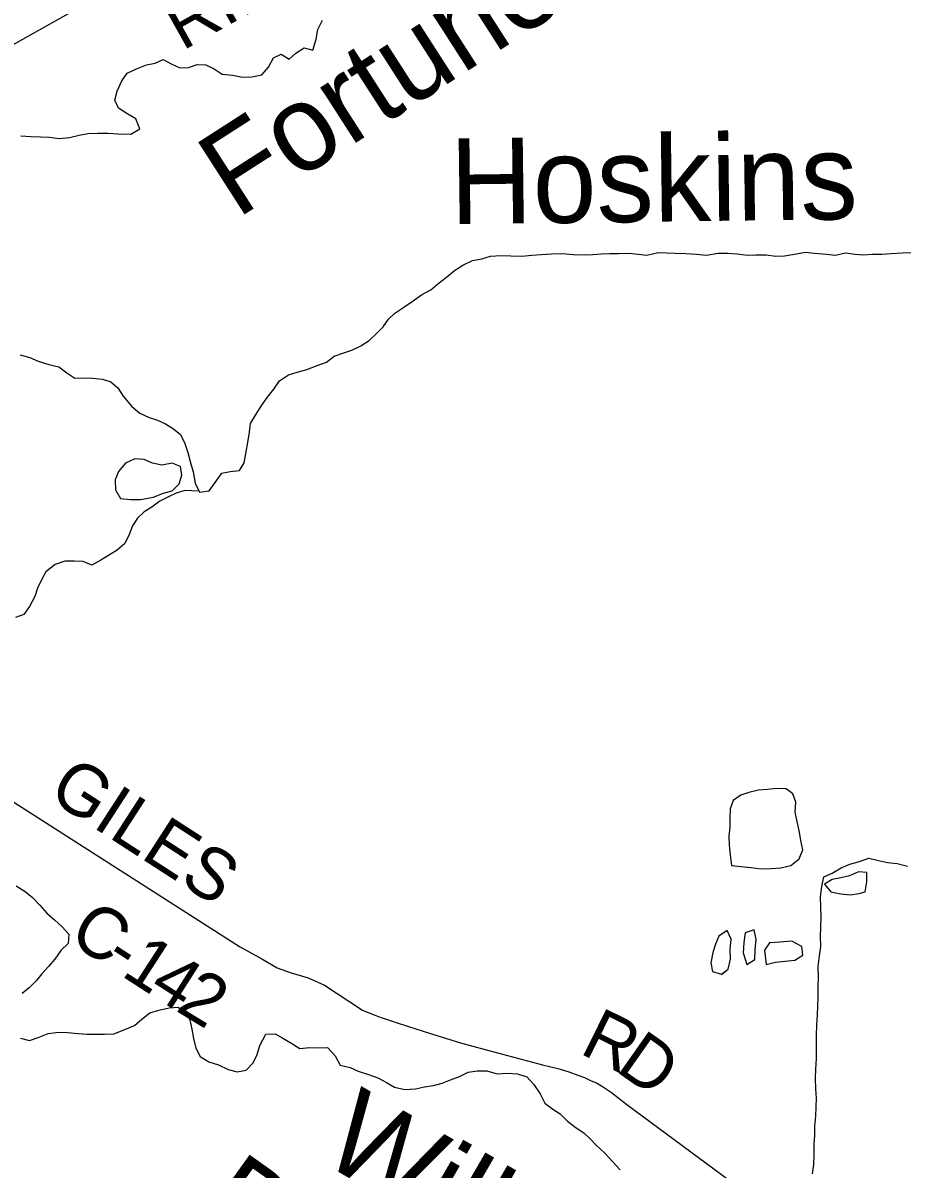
# Model space of a CAD drawing. Extents: x 1857828 to 2277390, y 930619 to 1324581.
# Drawn here: x 2092099 to 2097229, y 1210395 to 1217082 of the extents above; entities that cross this region are included whole.
import ezdxf

# ---------------------------------------------------------------- set-up
doc = ezdxf.new("R2010")
doc.units = 0
for name, color, linetype in [('GM_X_County_Road', 7, 'Continuous'), ('GM_X_County_Road_Text', 7, 'Continuous'), ('GM_X_Minor_Lake', 7, 'Continuous'), ('GM_X_Minor_River', 7, 'Continuous'), ('GM_X_Minor_River_Text', 7, 'Continuous'), ('GM_X_Township_Road', 7, 'Continuous'), ('GM_X_Township_Road_Text', 7, 'Continuous')]:
    doc.layers.add(name, color=color, linetype=linetype)

msp = doc.modelspace()

# ---------------------------------------------------------------- linework, layer by layer
at = {"layer": 'GM_X_County_Road'}
msp.add_lwpolyline([(2091976.3, 1212580.7), (2093362.3, 1211694.5), (2093493.1, 1211621.9), (2093583.1, 1211569.6), (2093664.5, 1211540.5), (2093763.3, 1211511.5), (2093859.2, 1211467.9), (2094080, 1211322.3), (2094152.2, 1211292.6), (2094194.4, 1211276.8), (2094288.7, 1211247.3), (2094483.2, 1211184.3), (2094651.7, 1211131.2), (2094868.3, 1211072.4), (2095131, 1211003.8), (2095227.3, 1210980.3), (2095283.5, 1210962.6), (2095337.6, 1210942.9), (2095375.8, 1210929), (2095413.9, 1210909.2), (2095446, 1210897.4), (2095480.2, 1210877.5), (2095532.5, 1210841.7), (2095622.9, 1210772.1), (2097802.5, 1209160.4)], dxfattribs=at)
at = {"layer": 'GM_X_Minor_Lake'}
for points in [[(2092855.2, 1214512.6), (2092807, 1214534.4), (2092752.8, 1214538.1), (2092696.8, 1214513.6), (2092657, 1214465.2), (2092637.2, 1214416.8), (2092639.5, 1214358.6), (2092667.9, 1214306.5), (2092728, 1214300.8), (2092784.2, 1214301.2), (2092860.3, 1214315.7)], [(2092860.3, 1214315.7), (2092916.4, 1214338.1), (2092970.4, 1214352.5), (2093010.3, 1214393), (2093026.1, 1214443.3), (2093017.8, 1214493.5), (2092969.6, 1214513.3), (2092909.5, 1214500.9), (2092855.2, 1214512.6)], [(2096629.4, 1212361.4), (2096617, 1212423.7), (2096604.7, 1212477.8), (2096608.3, 1212536.1), (2096592, 1212584.2), (2096551.8, 1212614.1), (2096495.6, 1212615.8), (2096443.5, 1212609.5), (2096391.4, 1212605.1), (2096335.3, 1212592.7), (2096287.2, 1212576.4), (2096243.3, 1212546), (2096225.5, 1212497.6), (2096223.8, 1212445.4), (2096224.1, 1212389.1)], [(2096224.1, 1212389.1), (2096218.4, 1212336.9), (2096220.7, 1212284.6), (2096225, 1212228.4), (2096233.3, 1212166.2), (2096289.5, 1212160.5), (2096347.7, 1212154.8), (2096405.9, 1212147.1), (2096464.1, 1212149.5), (2096522.2, 1212151.8), (2096580.3, 1212166.3), (2096628.2, 1212204.7), (2096650, 1212257.1), (2096637.7, 1212311.3), (2096629.4, 1212361.4)], [(2097014.3, 1212012.2), (2097024, 1212070.5), (2097023.7, 1212124.7), (2096973.6, 1212128.5), (2096921.6, 1212106), (2096871.5, 1212093.7)], [(2096871.5, 1212093.7), (2096821.4, 1212085.3), (2096775.4, 1212056.9), (2096813.8, 1212013), (2096872, 1212001.3), (2096926.2, 1211995.6), (2096978.3, 1212001.9), (2097014.3, 1212012.2)], [(2096175.2, 1211531.3), (2096214.6, 1211561.3), (2096228.3, 1211619.6), (2096226, 1211675.9), (2096231.7, 1211736.2), (2096207.3, 1211786.3), (2096159.4, 1211753.8)], [(2096174.6, 1211530.9), (2096214.6, 1211561.3), (2096228.3, 1211619.6), (2096226, 1211675.9), (2096231.7, 1211736.2), (2096207.3, 1211786.3), (2096159.4, 1211753.8)], [(2096378.1, 1211735.1), (2096365.7, 1211791.3), (2096313.7, 1211772.9), (2096306, 1211716.6), (2096302.3, 1211656.3), (2096322.9, 1211588.2)], [(2096159.4, 1211753.8), (2096139.6, 1211707.5), (2096123.8, 1211659.2), (2096112.1, 1211598.8), (2096122.4, 1211548.7), (2096175.2, 1211531.3)], [(2096322.7, 1211588.1), (2096368.7, 1211618.5), (2096372.4, 1211674.8), (2096378.1, 1211735.1)], [(2096322.9, 1211588.2), (2096368.7, 1211618.5), (2096372.4, 1211674.8), (2096378.1, 1211735.1)], [(2096584.7, 1211724.3), (2096516.5, 1211719.8), (2096454.4, 1211715.4), (2096426.6, 1211673.1), (2096435, 1211588.7)], [(2096435, 1211588.7), (2096491.1, 1211603.1), (2096547.2, 1211607.5), (2096603.4, 1211613.9), (2096649.3, 1211642.3), (2096643, 1211694.5), (2096584.7, 1211724.3)]]:
    msp.add_lwpolyline(points, dxfattribs=at)
at = {"layer": 'GM_X_Minor_River'}
for points in [[(2093065.2, 1216822.5), (2093115.3, 1216838.9), (2093165.4, 1216837.2), (2093215.7, 1216813.4), (2093262, 1216783.5), (2093322.2, 1216777.8), (2093380.4, 1216766.1), (2093434.6, 1216766.5), (2093492.6, 1216778.9), (2093532.5, 1216823.3), (2093560.3, 1216877.7), (2093606.3, 1216900.1), (2093652.6, 1216870.3), (2093690.5, 1216904.6), (2093740.5, 1216937.1), (2093790.7, 1216923.3), (2093810.4, 1216987.8), (2093820.1, 1217044.1), (2093847.9, 1217098.5)], [(2092086.7, 1216422.7), (2092144.9, 1216419.1), (2092201.1, 1216417.4), (2092251.2, 1216415.7), (2092311.4, 1216408), (2092371.6, 1216412.4), (2092427.6, 1216426.8), (2092477.7, 1216437.2), (2092535.9, 1216437.5), (2092596, 1216437.9), (2092652.2, 1216434.2), (2092728.4, 1216432.7), (2092780.4, 1216463.1), (2092758, 1216521.3), (2092711.8, 1216549.1), (2092657.4, 1216584.9), (2092635.1, 1216631), (2092648.9, 1216683.3), (2092676.6, 1216743.8), (2092706.4, 1216788.2), (2092762.5, 1216814.6), (2092820.5, 1216837.1), (2092870.6, 1216847.4), (2092916.6, 1216867.8), (2092964.9, 1216842), (2093015.1, 1216820.2), (2093065.2, 1216822.5)], [(2093104.6, 1214397.6), (2093128.9, 1214343.4), (2093185, 1214351.8), (2093220.9, 1214400.3), (2093258.7, 1214454.7), (2093308.7, 1214465.1), (2093362.9, 1214471.4), (2093390.7, 1214515.8), (2093402.4, 1214580.2), (2093412.1, 1214634.5), (2093421.8, 1214694.8), (2093427.5, 1214745.1), (2093455.4, 1214793.5), (2093493.1, 1214852), (2093527, 1214898.4), (2093562.8, 1214944.8), (2093596.7, 1214993.3), (2093648.6, 1215027.7), (2093698.7, 1215044.1), (2093754.7, 1215060.5), (2093816.8, 1215083), (2093870.8, 1215103.4), (2093914.7, 1215137.8), (2093970.8, 1215156.3), (2094018.8, 1215172.6), (2094070.9, 1215197.1), (2094118.8, 1215229.5), (2094160.7, 1215267.9), (2094200.6, 1215308.4), (2094232.5, 1215352.8), (2094268.4, 1215389.1), (2094322.3, 1215423.6), (2094370.3, 1215456.1), (2094424.2, 1215494.6), (2094478.2, 1215525), (2094520.1, 1215559.4), (2094570, 1215597.9), (2094618, 1215636.4), (2094665.9, 1215668.8), (2094721.9, 1215695.3), (2094776, 1215705.7), (2094828.1, 1215720), (2094888.2, 1215724.4), (2094946.4, 1215722.8), (2095010.6, 1215721.1), (2095068.7, 1215727.5), (2095124.9, 1215729.9), (2095183, 1215734.2), (2095247.2, 1215736.6), (2095309.4, 1215731), (2095373.5, 1215729.4), (2095423.7, 1215729.7), (2095473.8, 1215734), (2095523.9, 1215736.3), (2095576.1, 1215736.6), (2095634.2, 1215739), (2095688.4, 1215733.3), (2095738.6, 1215727.6), (2095804.7, 1215742), (2095854.8, 1215740.3), (2095905, 1215738.6), (2095967.1, 1215737), (2096029.3, 1215733.3), (2096087.5, 1215727.7), (2096155.7, 1215738.1), (2096209.8, 1215738.4), (2096266, 1215734.8), (2096324.2, 1215727.1), (2096376.3, 1215729.4), (2096436.5, 1215727.8), (2096492.7, 1215720.1), (2096542.8, 1215722.4), (2096612.9, 1215734.9), (2096663, 1215745.2), (2096717.2, 1215737.5), (2096787.4, 1215731.9), (2096837.6, 1215726.2), (2096899.7, 1215740.6), (2096953.9, 1215732.9), (2097004.1, 1215729.2), (2097056.2, 1215733.5), (2097110.3, 1215731.8), (2097164.5, 1215736.2), (2097228.6, 1215740.6), (2097284.8, 1215742.9)], [(2092083.7, 1215144.8), (2092139.9, 1215129.1), (2092188.2, 1215109.3), (2092250.4, 1215089.6), (2092308.7, 1215075.9), (2092355, 1215040), (2092401.3, 1215010.1), (2092451.4, 1215010.4), (2092507.6, 1215008.8), (2092563.8, 1215003.1), (2092612, 1214987.3), (2092652.3, 1214953.4), (2092684.6, 1214903.3), (2092735.1, 1214843.4), (2092781.4, 1214805.5), (2092835.7, 1214779.7), (2092884, 1214763.9), (2092930.2, 1214742.1), (2092978.5, 1214714.2), (2093018.8, 1214680.3), (2093043.1, 1214628.2), (2093061.5, 1214576.1), (2093075.8, 1214524), (2093092.2, 1214461.8), (2093104.6, 1214397.6)], [(2093125.8, 1214350.3), (2093044.6, 1214353), (2092992.6, 1214338.6), (2092944.6, 1214314.2), (2092898.6, 1214291.8), (2092850.6, 1214257.4), (2092806.7, 1214229), (2092766.7, 1214192.6), (2092738.9, 1214148.2), (2092719.1, 1214097.8), (2092693.3, 1214045.4), (2092649.4, 1214005), (2092603.5, 1213978.6), (2092553.5, 1213948.2), (2092501.5, 1213917.7), (2092451.3, 1213939.5), (2092397.1, 1213941.2), (2092343, 1213940.9), (2092286.9, 1213922.4), (2092233, 1213879.9), (2092207.2, 1213833.5), (2092183.4, 1213783.2), (2092167.6, 1213734.8), (2092137.8, 1213676.4), (2092104, 1213630), (2092056, 1213613.6)], [(2096706.5, 1210366.8), (2096714.2, 1210421.1), (2096715.9, 1210475.4), (2096715.5, 1210539.7), (2096719.3, 1210591.9), (2096719, 1210646.2), (2096724.7, 1210704.5), (2096728.4, 1210758.7), (2096730.1, 1210809), (2096725.8, 1210863.2), (2096723.5, 1210925.5), (2096725.2, 1210977.7), (2096728.8, 1211040), (2096730.4, 1211114.4), (2096730.1, 1211172.6), (2096731.8, 1211238.9), (2096735.5, 1211293.2), (2096737.2, 1211347.5), (2096738.9, 1211397.7), (2096738.6, 1211458), (2096740.3, 1211516.2), (2096739.9, 1211576.5), (2096747.6, 1211638.9), (2096755.4, 1211693.2), (2096753, 1211751.4), (2096754.7, 1211807.7), (2096756.4, 1211868), (2096754.1, 1211920.2), (2096753.8, 1211982.5), (2096761.5, 1212042.8), (2096773.2, 1212099.1), (2096821.2, 1212121.5), (2096873.2, 1212152), (2096923.2, 1212174.4), (2096981.3, 1212188.8), (2097035.3, 1212209.2), (2097091.5, 1212195.5), (2097143.7, 1212183.7), (2097199.9, 1212178.1), (2097260.2, 1212162.3)], [(2092060.5, 1212048.5), (2092112.8, 1212014.6), (2092155.2, 1211978.7), (2092197.5, 1211934.8), (2092237.9, 1211888.8), (2092284.2, 1211848.9), (2092328.5, 1211809), (2092366.9, 1211765), (2092363.2, 1211710.8), (2092319.3, 1211670.3), (2092285.5, 1211619.9), (2092247.6, 1211577.4), (2092209.7, 1211535), (2092177.9, 1211494.6), (2092136, 1211452.2), (2092094, 1211419.8)], [(2092085.4, 1211158.6), (2092137.7, 1211144.8), (2092187.7, 1211163.2), (2092245.7, 1211185.6), (2092305.8, 1211194.1), (2092360, 1211192.4), (2092422.2, 1211186.7), (2092472.4, 1211183), (2092522.5, 1211181.3), (2092574.7, 1211181.6), (2092628.8, 1211184), (2092684.8, 1211206.4), (2092750.9, 1211232.9), (2092792.8, 1211269.3), (2092838.7, 1211305.8), (2092892.8, 1211322.2), (2092952.8, 1211336.6), (2093003, 1211338.9), (2093049.2, 1211311.1), (2093073.6, 1211265)], [(2093073.6, 1211265), (2093083.9, 1211210.8), (2093094.2, 1211156.6), (2093108.6, 1211100.5), (2093132.9, 1211052.4), (2093183.2, 1211020.6), (2093239.5, 1211002.8), (2093295.8, 1210977), (2093350, 1210963.3), (2093402.1, 1210971.6), (2093442, 1211014.1), (2093465.7, 1211064.5), (2093481.5, 1211116.8), (2093517.2, 1211181.3), (2093571.4, 1211183.6), (2093615.6, 1211159.8), (2093661.9, 1211131.9), (2093714.2, 1211098.1), (2093772.4, 1211104.5), (2093826.5, 1211102.8), (2093876.6, 1211105.1), (2093921, 1211055.2), (2093949.4, 1211001.1), (2094007.6, 1210987.4), (2094055.9, 1210965.6), (2094116.2, 1210947.8), (2094170.4, 1210928.1), (2094220.7, 1210900.3), (2094267, 1210872.4), (2094327.2, 1210858.7), (2094389.4, 1210863.1), (2094441.5, 1210875.5), (2094495.6, 1210881.8), (2094545.6, 1210896.2), (2094593.7, 1210916.6), (2094645.7, 1210935), (2094697.7, 1210961.4), (2094749.8, 1210967.8), (2094806, 1210968.1), (2094866.2, 1210950.4), (2094924.4, 1210954.8), (2094984.5, 1210951.1), (2095038.8, 1210933.3), (2095081.1, 1210889.4), (2095117.5, 1210833.4), (2095143.9, 1210779.3), (2095190.2, 1210745.4), (2095234.5, 1210717.5), (2095276.8, 1210675.6), (2095327.2, 1210635.7), (2095371.5, 1210605.9), (2095409.8, 1210571.9), (2095444.1, 1210534), (2095494.5, 1210488.1), (2095538.9, 1210440.1), (2095583.2, 1210390.1)]]:
    msp.add_lwpolyline(points, dxfattribs=at)
at = {"layer": 'GM_X_Township_Road'}
msp.add_lwpolyline([(2091988, 1216924.6), (2096153.5, 1219265.3), (2098467.5, 1220557.9), (2098671.1, 1220669.6), (2098914.7, 1220801.5), (2099082.4, 1220900.9), (2099269.2, 1221041)], dxfattribs=at)

# ---------------------------------------------------------------- texts
at = {"layer": 'GM_X_County_Road_Text'}
for s, rotation, p in [('GILES', 327.11935, (2092235.9, 1212564.3)), ('C', 327.04387, (2092354.7, 1211728.6)), ('1', 327.13972, (2092665.3, 1211527.3)), ('-', 327.06598, (2092561.5, 1211594.5)), ('4', 327.45758, (2092822, 1211426.1)), ('2', 328.53918, (2092983, 1211323.4)), ('R', 333.66536, (2095340.3, 1211074.2)), ('D', 324.93576, (2095550.7, 1210971))]:
    msp.add_text(s, height=300, rotation=rotation, dxfattribs=at).set_placement(p)
at = {"layer": 'GM_X_Minor_River_Text'}
for s, rotation, p in [('Fortune', 32.72974, (2093346.3, 1215934.9)), ('Hoskins', 0.72776, (2094593.1, 1215906.9)), ('Willow', 329.98973, (2093819.3, 1210448.3)), ('Ditch', 324.55932, (2093086.8, 1210103.3))]:
    msp.add_text(s, height=500.27, rotation=rotation, dxfattribs=at).set_placement(p)
at = {"layer": 'GM_X_Township_Road_Text'}
msp.add_text('RIDGE RD', height=300, rotation=29.25421, dxfattribs=at).set_placement((2093029.4, 1216916.4))

doc.saveas('drawing.dxf')
